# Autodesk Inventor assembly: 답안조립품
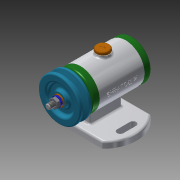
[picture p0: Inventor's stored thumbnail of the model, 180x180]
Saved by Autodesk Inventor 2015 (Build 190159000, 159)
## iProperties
Created: 2021-09
Part Number: 답안조립품
Document SubType Name: Assembly
Designer: now
Author: now
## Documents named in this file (14)
- C:\Users\now\Desktop\710906V1008\답안조립품.iam
- C:\Users\now\Desktop\710906V1008\V벨트풀리.ipt
- C:\Users\now\Desktop\710906V1008\너트 M8.ipt
- C:\Users\now\Desktop\710906V1008\뒤커버.ipt
- C:\Users\now\Desktop\710906V1008\베어링 15x32x9.ipt
- C:\Users\now\Desktop\710906V1008\본체.ipt
- C:\Users\now\Desktop\710906V1008\볼트 M4x12.ipt
- C:\Users\now\Desktop\710906V1008\스프링와셔 8.ipt
- C:\Users\now\Desktop\710906V1008\앞커버.ipt
- C:\Users\now\Desktop\710906V1008\오일 실 15x25x7.ipt
- C:\Users\now\Desktop\710906V1008\와셔 8x17.ipt
- C:\Users\now\Desktop\710906V1008\축.ipt
- C:\Users\now\Desktop\710906V1008\캡.ipt
- C:\Users\now\Desktop\710906V1008\키 3x3.ipt
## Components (1 placed, 1 different names)
1. V벨트풀리:1 — 각도:2
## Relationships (1: Angle 1)
- 각도:2 [Angle]: V벨트풀리:1
